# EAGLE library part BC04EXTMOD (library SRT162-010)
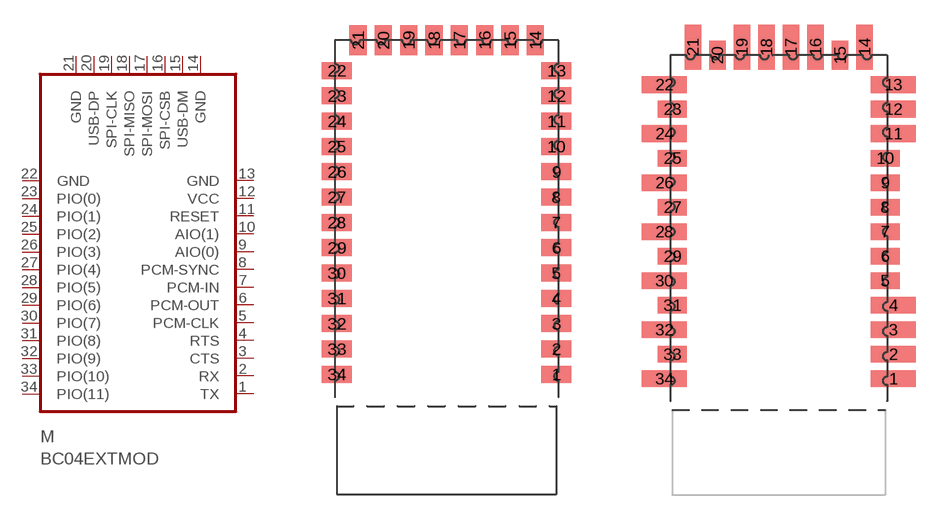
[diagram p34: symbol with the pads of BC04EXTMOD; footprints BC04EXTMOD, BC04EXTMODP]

Designator prefix M

## BC04EXTMOD  [BC04EXTMOD]
1  TX  pas
2  RX  pas
3  CTS  pas
4  RTS  pas
5  PCM-CLK  pas
6  PCM-OUT  pas
7  PCM-IN  pas
8  PCM-SYNC  pas
9  AIO(0)  pas
10  AIO(1)  pas
11  RESET  pas
12  VCC  pwr
13  GND  pwr
14  GND  pwr
15  USB-DM  pas
16  SPI-CSB  pas
17  SPI-MOSI  pas
18  SPI-MISO  pas
19  SPI-CLK  pas
20  USB-DP  pas
21  GND  pwr
22  GND  pwr
23  PIO(0)  pas
24  PIO(1)  pas
25  PIO(2)  pas
26  PIO(3)  pas
27  PIO(4)  pas
28  PIO(5)  pas
29  PIO(6)  pas
30  PIO(7)  pas
31  PIO(8)  pas
32  PIO(9)  pas
33  PIO(10)  pas
34  PIO(11)  pas

## BC04EXTMODP  [BC04EXTMODP]
Pads as for BC04EXTMOD

## Footprint BC04EXTMOD (pad centres in mm)
smd 1.778 x 1.016: 1 6.5,-8.487; 2 6.5,-6.987; 3 6.5,-5.487; 4 6.5,-3.987; 5 6.5,-2.487; 6 6.5,-0.987; 7 6.5,0.513; 8 6.5,2.013; 9 6.5,3.513; 10 6.5,5.013; 11 6.5,6.513; 12 6.5,8.013; 13 6.5,9.513; 22 -6.5,9.513; 23 -6.5,8.013; 24 -6.5,6.513; 25 -6.5,5.013; 26 -6.5,3.513; 27 -6.5,2.013; 28 -6.5,0.513; 29 -6.5,-0.987; 30 -6.5,-2.487; 31 -6.5,-3.987; 32 -6.5,-5.487; 33 -6.5,-6.987; 34 -6.5,-8.487
smd 1.016 x 1.778: 14 5.25,11.303; 15 3.75,11.303; 16 2.25,11.303; 17 0.75,11.303; 18 -0.75,11.303; 19 -2.25,11.303; 20 -3.75,11.303; 21 -5.25,11.303

## Footprint BC04EXTMODP (pad centres in mm)
smd 2.778 x 1.016: 1 7,-8.487; 2 7,-6.987; 3 7,-5.487; 4 7,-3.987; 11 7,6.513; 12 7,8.013; 13 7,9.513; 22 -7,9.513; 24 -7,6.513; 26 -7,3.513; 28 -7,0.513; 30 -7,-2.487; 32 -7,-5.487; 34 -7,-8.487
smd 1.778 x 1.016: 5 6.5,-2.487; 6 6.5,-0.987; 7 6.5,0.513; 8 6.5,2.013; 9 6.5,3.513; 10 6.5,5.013; 23 -6.5,8.013; 25 -6.5,5.013; 27 -6.5,2.013; 29 -6.5,-0.987; 31 -6.5,-3.987; 33 -6.5,-6.987
smd 1.016 x 2.778: 14 5.25,11.803; 16 2.25,11.803; 17 0.75,11.803; 18 -0.75,11.803; 19 -2.25,11.803; 21 -5.25,11.803
smd 1.016 x 1.778: 15 3.75,11.303; 20 -3.75,11.303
